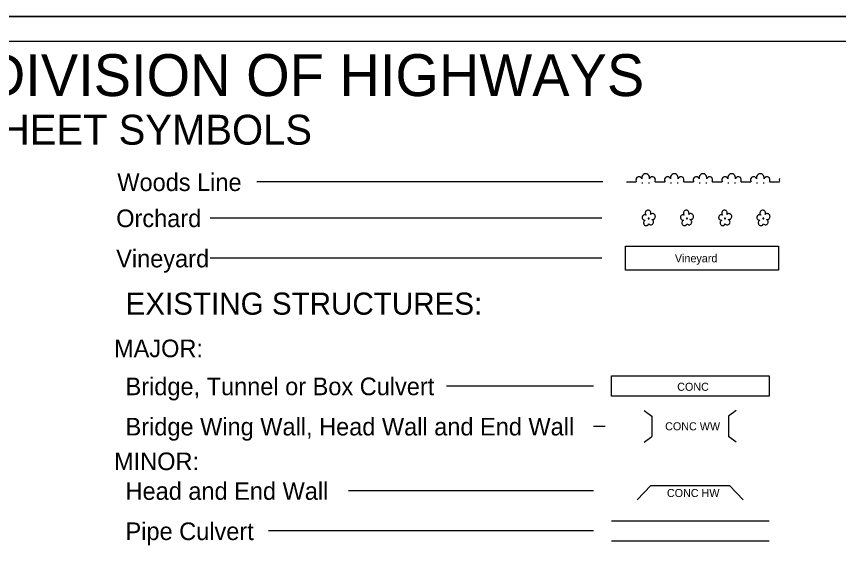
# Model space of a CAD drawing. Extents: x 2025847 to 2026166, y 840763 to 840870.
# Drawn here: x 2026094.71 to 2026130.13, y 840846.96 to 840870.09 of the extents above; entities that cross this region are included whole.
import ezdxf

# ---------------------------------------------------------------- set-up
doc = ezdxf.new("R2010")
doc.units = 0
for name, color, linetype in [('Sheet_Plan', 7, 'Continuous'), ('Sheet_Plot_Border_Outside_CELL', 7, 'Continuous'), ('Sheet_Symbology', 7, 'Continuous'), ('z - Construction', 7, 'Continuous')]:
    doc.layers.add(name, color=color, linetype=linetype)

msp = doc.modelspace()

# ---------------------------------------------------------------- linework, layer by layer
at = {"layer": 'Sheet_Plan'}
msp.add_line((2026164.548, 840869.009), (2026024.668, 840869.009), dxfattribs=at)
at = {"layer": 'Sheet_Plot_Border_Outside_CELL'}
msp.add_lwpolyline([(2026023.879, 840870.085), (2026165.546, 840870.085), (2026165.546, 840778.419), (2026023.879, 840778.419)], close=True, dxfattribs=at)
at = {"layer": 'Sheet_Symbology'}
for p, q in [((2026119.979, 840862.96), (2026105.07, 840862.96)), ((2026121, 840862.96), (2026121.411, 840862.96)), ((2026122.234, 840862.96), (2026122.646, 840862.96)), ((2026123.469, 840862.96), (2026123.881, 840862.96)), ((2026124.704, 840862.96), (2026125.115, 840862.96)), ((2026125.939, 840862.96), (2026126.35, 840862.96)), ((2026127.173, 840862.96), (2026127.585, 840862.96)), ((2026121.654, 840862.916), (2026121.695, 840862.916)), ((2026121.942, 840862.916), (2026121.983, 840862.916)), ((2026122.889, 840862.916), (2026122.93, 840862.916)), ((2026123.177, 840862.916), (2026123.218, 840862.916)), ((2026124.124, 840862.916), (2026124.165, 840862.916)), ((2026124.412, 840862.916), (2026124.453, 840862.916)), ((2026125.358, 840862.916), (2026125.399, 840862.916)), ((2026125.646, 840862.916), (2026125.688, 840862.916)), ((2026126.593, 840862.916), (2026126.634, 840862.916)), ((2026126.881, 840862.916), (2026126.922, 840862.916)), ((2026119.933, 840861.406), (2026103.063, 840861.406)), ((2026119.933, 840859.673), (2026103.063, 840859.673)), ((2026119.578, 840854.171), (2026113.242, 840854.171)), ((2026121.755, 840853.119), (2026122.092, 840852.871)), ((2026125.723, 840853.119), (2026125.385, 840852.871)), ((2026122.092, 840852.871), (2026122.092, 840852.004)), ((2026125.385, 840852.871), (2026125.385, 840852.004)), ((2026119.578, 840852.438), (2026120.071, 840852.438)), ((2026121.755, 840851.756), (2026122.092, 840852.004)), ((2026125.723, 840851.756), (2026125.385, 840852.004)), ((2026121.459, 840849.269), (2026122.041, 840849.882)), ((2026122.041, 840849.882), (2026125.437, 840849.882)), ((2026125.437, 840849.882), (2026126.019, 840849.269)), ((2026119.578, 840849.665), (2026109.016, 840849.665)), ((2026120.343, 840848.366), (2026127.134, 840848.366)), ((2026119.578, 840847.932), (2026105.568, 840847.932)), ((2026120.343, 840847.499), (2026127.134, 840847.499))]:
    msp.add_line(p, q, dxfattribs=at)
for points in [[(2026122.027, 840861.558), (2026122.04, 840861.584), (2026122.044, 840861.61), (2026122.04, 840861.636), (2026122.036, 840861.662), (2026122.023, 840861.684), (2026122.011, 840861.705), (2026121.99, 840861.723), (2026121.97, 840861.736), (2026121.941, 840861.744), (2026121.92, 840861.744), (2026121.896, 840861.74), (2026121.871, 840861.731), (2026121.85, 840861.718), (2026121.83, 840861.701), (2026121.817, 840861.675), (2026121.809, 840861.653), (2026121.805, 840861.627), (2026121.805, 840861.601), (2026121.809, 840861.575), (2026121.822, 840861.554), (2026121.838, 840861.528), (2026121.817, 840861.541), (2026121.793, 840861.545), (2026121.768, 840861.545), (2026121.747, 840861.536), (2026121.727, 840861.528), (2026121.706, 840861.51), (2026121.69, 840861.493), (2026121.677, 840861.471), (2026121.673, 840861.45), (2026121.669, 840861.419), (2026121.673, 840861.398), (2026121.682, 840861.376), (2026121.698, 840861.354), (2026121.71, 840861.337), (2026121.731, 840861.324), (2026121.756, 840861.311), (2026121.776, 840861.307), (2026121.801, 840861.307), (2026121.78, 840861.298), (2026121.76, 840861.281), (2026121.747, 840861.263), (2026121.739, 840861.237), (2026121.731, 840861.211), (2026121.731, 840861.19), (2026121.735, 840861.164), (2026121.747, 840861.142), (2026121.76, 840861.12), (2026121.776, 840861.103), (2026121.797, 840861.09), (2026121.817, 840861.081), (2026121.842, 840861.081), (2026121.867, 840861.081), (2026121.887, 840861.086), (2026121.908, 840861.103), (2026121.929, 840861.116), (2026121.949, 840861.155)], [(2026121.949, 840861.155), (2026121.998, 840861.125), (2026122.023, 840861.116), (2026122.048, 840861.112), (2026122.073, 840861.116), (2026122.093, 840861.125), (2026122.114, 840861.138), (2026122.134, 840861.155), (2026122.147, 840861.177), (2026122.155, 840861.198), (2026122.163, 840861.224), (2026122.159, 840861.25), (2026122.155, 840861.276), (2026122.138, 840861.302), (2026122.126, 840861.32), (2026122.105, 840861.333), (2026122.081, 840861.346), (2026122.105, 840861.341), (2026122.134, 840861.341), (2026122.155, 840861.35), (2026122.18, 840861.363), (2026122.2, 840861.376), (2026122.217, 840861.398), (2026122.229, 840861.424), (2026122.233, 840861.45), (2026122.237, 840861.476), (2026122.233, 840861.502), (2026122.225, 840861.528), (2026122.208, 840861.549), (2026122.188, 840861.571), (2026122.167, 840861.584), (2026122.143, 840861.593), (2026122.118, 840861.597), (2026122.093, 840861.597), (2026122.068, 840861.588), (2026122.048, 840861.575), (2026122.027, 840861.558)], [(2026123.674, 840861.558), (2026123.686, 840861.584), (2026123.69, 840861.61), (2026123.686, 840861.636), (2026123.682, 840861.662), (2026123.67, 840861.684), (2026123.657, 840861.705), (2026123.637, 840861.723), (2026123.616, 840861.736), (2026123.587, 840861.744), (2026123.567, 840861.744), (2026123.542, 840861.74), (2026123.517, 840861.731), (2026123.497, 840861.718), (2026123.476, 840861.701), (2026123.464, 840861.675), (2026123.455, 840861.653), (2026123.451, 840861.627), (2026123.451, 840861.601), (2026123.455, 840861.575), (2026123.468, 840861.554), (2026123.484, 840861.528), (2026123.464, 840861.541), (2026123.439, 840861.545), (2026123.414, 840861.545), (2026123.394, 840861.536), (2026123.373, 840861.528), (2026123.353, 840861.51), (2026123.336, 840861.493), (2026123.324, 840861.471), (2026123.32, 840861.45), (2026123.316, 840861.419), (2026123.32, 840861.398), (2026123.328, 840861.376), (2026123.344, 840861.354), (2026123.357, 840861.337), (2026123.377, 840861.324), (2026123.402, 840861.311), (2026123.423, 840861.307), (2026123.447, 840861.307), (2026123.427, 840861.298), (2026123.406, 840861.281), (2026123.394, 840861.263), (2026123.386, 840861.237), (2026123.377, 840861.211), (2026123.377, 840861.19), (2026123.381, 840861.164), (2026123.394, 840861.142), (2026123.406, 840861.12), (2026123.423, 840861.103), (2026123.443, 840861.09), (2026123.464, 840861.081), (2026123.488, 840861.081), (2026123.513, 840861.081), (2026123.534, 840861.086), (2026123.554, 840861.103), (2026123.575, 840861.116), (2026123.595, 840861.155)], [(2026123.595, 840861.155), (2026123.645, 840861.125), (2026123.67, 840861.116), (2026123.694, 840861.112), (2026123.719, 840861.116), (2026123.739, 840861.125), (2026123.76, 840861.138), (2026123.781, 840861.155), (2026123.793, 840861.177), (2026123.801, 840861.198), (2026123.809, 840861.224), (2026123.805, 840861.25), (2026123.801, 840861.276), (2026123.785, 840861.302), (2026123.772, 840861.32), (2026123.752, 840861.333), (2026123.727, 840861.346), (2026123.752, 840861.341), (2026123.781, 840861.341), (2026123.801, 840861.35), (2026123.826, 840861.363), (2026123.846, 840861.376), (2026123.863, 840861.398), (2026123.875, 840861.424), (2026123.879, 840861.45), (2026123.884, 840861.476), (2026123.879, 840861.502), (2026123.871, 840861.528), (2026123.855, 840861.549), (2026123.834, 840861.571), (2026123.814, 840861.584), (2026123.789, 840861.593), (2026123.764, 840861.597), (2026123.739, 840861.597), (2026123.715, 840861.588), (2026123.694, 840861.575), (2026123.674, 840861.558)], [(2026125.32, 840861.558), (2026125.332, 840861.584), (2026125.336, 840861.61), (2026125.332, 840861.636), (2026125.328, 840861.662), (2026125.316, 840861.684), (2026125.303, 840861.705), (2026125.283, 840861.723), (2026125.262, 840861.736), (2026125.234, 840861.744), (2026125.213, 840861.744), (2026125.188, 840861.74), (2026125.164, 840861.731), (2026125.143, 840861.718), (2026125.122, 840861.701), (2026125.11, 840861.675), (2026125.102, 840861.653), (2026125.098, 840861.627), (2026125.098, 840861.601), (2026125.102, 840861.575), (2026125.114, 840861.554), (2026125.131, 840861.528), (2026125.11, 840861.541), (2026125.085, 840861.545), (2026125.061, 840861.545), (2026125.04, 840861.536), (2026125.02, 840861.528), (2026124.999, 840861.51), (2026124.982, 840861.493), (2026124.97, 840861.471), (2026124.966, 840861.45), (2026124.962, 840861.419), (2026124.966, 840861.398), (2026124.974, 840861.376), (2026124.991, 840861.354), (2026125.003, 840861.337), (2026125.024, 840861.324), (2026125.048, 840861.311), (2026125.069, 840861.307), (2026125.094, 840861.307), (2026125.073, 840861.298), (2026125.052, 840861.281), (2026125.04, 840861.263), (2026125.032, 840861.237), (2026125.024, 840861.211), (2026125.024, 840861.19), (2026125.028, 840861.164), (2026125.04, 840861.142), (2026125.052, 840861.12), (2026125.069, 840861.103), (2026125.089, 840861.09), (2026125.11, 840861.081), (2026125.135, 840861.081), (2026125.159, 840861.081), (2026125.18, 840861.086), (2026125.201, 840861.103), (2026125.221, 840861.116), (2026125.242, 840861.155)], [(2026125.242, 840861.155), (2026125.291, 840861.125), (2026125.316, 840861.116), (2026125.341, 840861.112), (2026125.365, 840861.116), (2026125.386, 840861.125), (2026125.406, 840861.138), (2026125.427, 840861.155), (2026125.439, 840861.177), (2026125.448, 840861.198), (2026125.456, 840861.224), (2026125.452, 840861.25), (2026125.448, 840861.276), (2026125.431, 840861.302), (2026125.419, 840861.32), (2026125.398, 840861.333), (2026125.373, 840861.346), (2026125.398, 840861.341), (2026125.427, 840861.341), (2026125.448, 840861.35), (2026125.472, 840861.363), (2026125.493, 840861.376), (2026125.509, 840861.398), (2026125.522, 840861.424), (2026125.526, 840861.45), (2026125.53, 840861.476), (2026125.526, 840861.502), (2026125.518, 840861.528), (2026125.501, 840861.549), (2026125.48, 840861.571), (2026125.46, 840861.584), (2026125.435, 840861.593), (2026125.411, 840861.597), (2026125.386, 840861.597), (2026125.361, 840861.588), (2026125.341, 840861.575), (2026125.32, 840861.558)], [(2026126.966, 840861.558), (2026126.979, 840861.584), (2026126.983, 840861.61), (2026126.979, 840861.636), (2026126.975, 840861.662), (2026126.962, 840861.684), (2026126.95, 840861.705), (2026126.929, 840861.723), (2026126.909, 840861.736), (2026126.88, 840861.744), (2026126.859, 840861.744), (2026126.835, 840861.74), (2026126.81, 840861.731), (2026126.789, 840861.718), (2026126.769, 840861.701), (2026126.756, 840861.675), (2026126.748, 840861.653), (2026126.744, 840861.627), (2026126.744, 840861.601), (2026126.748, 840861.575), (2026126.761, 840861.554), (2026126.777, 840861.528), (2026126.756, 840861.541), (2026126.732, 840861.545), (2026126.707, 840861.545), (2026126.686, 840861.536), (2026126.666, 840861.528), (2026126.645, 840861.51), (2026126.629, 840861.493), (2026126.616, 840861.471), (2026126.612, 840861.45), (2026126.608, 840861.419), (2026126.612, 840861.398), (2026126.621, 840861.376), (2026126.637, 840861.354), (2026126.649, 840861.337), (2026126.67, 840861.324), (2026126.695, 840861.311), (2026126.715, 840861.307), (2026126.74, 840861.307), (2026126.719, 840861.298), (2026126.699, 840861.281), (2026126.686, 840861.263), (2026126.678, 840861.237), (2026126.67, 840861.211), (2026126.67, 840861.19), (2026126.674, 840861.164), (2026126.686, 840861.142), (2026126.699, 840861.12), (2026126.715, 840861.103), (2026126.736, 840861.09), (2026126.756, 840861.081), (2026126.781, 840861.081), (2026126.806, 840861.081), (2026126.826, 840861.086), (2026126.847, 840861.103), (2026126.868, 840861.116), (2026126.888, 840861.155)], [(2026126.888, 840861.155), (2026126.937, 840861.125), (2026126.962, 840861.116), (2026126.987, 840861.112), (2026127.012, 840861.116), (2026127.032, 840861.125), (2026127.053, 840861.138), (2026127.073, 840861.155), (2026127.086, 840861.177), (2026127.094, 840861.198), (2026127.102, 840861.224), (2026127.098, 840861.25), (2026127.094, 840861.276), (2026127.077, 840861.302), (2026127.065, 840861.32), (2026127.044, 840861.333), (2026127.02, 840861.346), (2026127.044, 840861.341), (2026127.073, 840861.341), (2026127.094, 840861.35), (2026127.119, 840861.363), (2026127.139, 840861.376), (2026127.156, 840861.398), (2026127.168, 840861.424), (2026127.172, 840861.45), (2026127.176, 840861.476), (2026127.172, 840861.502), (2026127.164, 840861.528), (2026127.147, 840861.549), (2026127.127, 840861.571), (2026127.106, 840861.584), (2026127.082, 840861.593), (2026127.057, 840861.597), (2026127.032, 840861.597), (2026127.007, 840861.588), (2026126.987, 840861.575), (2026126.966, 840861.558)], [(2026121.957, 840861.406), (2026121.945, 840861.406), (2026121.937, 840861.402), (2026121.929, 840861.398), (2026121.929, 840861.385), (2026121.929, 840861.376), (2026121.937, 840861.367), (2026121.949, 840861.367), (2026121.957, 840861.367), (2026121.966, 840861.376), (2026121.97, 840861.389), (2026121.966, 840861.398), (2026121.957, 840861.406)], [(2026123.604, 840861.406), (2026123.591, 840861.406), (2026123.583, 840861.402), (2026123.575, 840861.398), (2026123.575, 840861.385), (2026123.575, 840861.376), (2026123.583, 840861.367), (2026123.595, 840861.367), (2026123.604, 840861.367), (2026123.612, 840861.376), (2026123.616, 840861.389), (2026123.612, 840861.398), (2026123.604, 840861.406)], [(2026125.25, 840861.406), (2026125.238, 840861.406), (2026125.229, 840861.402), (2026125.221, 840861.398), (2026125.221, 840861.385), (2026125.221, 840861.376), (2026125.229, 840861.367), (2026125.242, 840861.367), (2026125.25, 840861.367), (2026125.258, 840861.376), (2026125.262, 840861.389), (2026125.258, 840861.398), (2026125.25, 840861.406)], [(2026126.896, 840861.406), (2026126.884, 840861.406), (2026126.876, 840861.402), (2026126.868, 840861.398), (2026126.868, 840861.385), (2026126.868, 840861.376), (2026126.876, 840861.367), (2026126.888, 840861.367), (2026126.896, 840861.367), (2026126.905, 840861.376), (2026126.909, 840861.389), (2026126.905, 840861.398), (2026126.896, 840861.406)], [(2026120.953, 840860.193), (2026127.538, 840860.193), (2026127.538, 840859.154), (2026120.953, 840859.154), (2026120.953, 840860.193)], [(2026120.343, 840854.604), (2026127.134, 840854.604), (2026127.134, 840853.737), (2026120.343, 840853.737), (2026120.343, 840854.604)]]:
    msp.add_lwpolyline(points, dxfattribs=at)
for centre, major_axis, start_param, end_param in [((2026121.819, 840863.134), (0, 0.179), 4.46741, 8.09896), ((2026123.053, 840863.134), (0, 0.179), 4.46741, 8.09896), ((2026124.288, 840863.134), (0, 0.179), 4.46741, 8.09896), ((2026125.523, 840863.134), (0, 0.179), 4.46741, 8.09896), ((2026126.757, 840863.134), (0, 0.179), 4.46741, 8.09896), ((2026121.531, 840863.048), (0, 0.137), 5.03414, 8.538701), ((2026122.107, 840863.048), (0, 0.137), 4.02767, 7.532231), ((2026122.765, 840863.048), (0, 0.137), 5.03414, 8.538701), ((2026123.341, 840863.048), (0, 0.137), 4.02767, 7.532231), ((2026124, 840863.048), (0, 0.137), 5.03414, 8.538701), ((2026124.576, 840863.048), (0, 0.137), 4.02767, 7.532231), ((2026125.235, 840863.048), (0, 0.137), 5.03414, 8.538701), ((2026125.811, 840863.048), (0, 0.137), 4.02767, 7.532231), ((2026126.469, 840863.048), (0, 0.137), 5.03414, 8.538701), ((2026127.046, 840863.048), (0, 0.137), 4.02767, 7.532231), ((2026127.704, 840863.048), (0, 0.137), 1.156298, 1.985294)]:
    msp.add_ellipse(centre, major_axis=major_axis, ratio=0.95, start_param=start_param, end_param=end_param, dxfattribs=at)
at = {"layer": 'z - Construction'}
msp.add_line((2026165.546, 840870.085), (2026023.879, 840870.085), dxfattribs=at)

# ---------------------------------------------------------------- texts
at = {"layer": 'Sheet_Symbology'}
for s, height, p in [('STATE OF NORTH CAROLINA, DIVISION OF HIGHWAYS', 1.80351, (2026057.976, 840866.657)), ('CONVENTIONAL  PLAN SHEET SYMBOLS', 1.28822, (2026073.367, 840864.564)), ('Woods Line', 0.7582, (2026099.058, 840862.568)), ('Orchard', 0.7582, (2026099.011, 840861.014)), ('Vineyard', 0.7582, (2026099.011, 840859.281)), ('EXISTING STRUCTURES:', 0.95314, (2026099.413, 840857.242)), ('MAJOR:', 0.7582, (2026098.917, 840855.413)), ('Bridge, Tunnel or Box Culvert', 0.75818, (2026099.413, 840853.776)), ('CONC', 0.3466, (2026123.178, 840853.966)), ('Bridge Wing Wall, Head Wall and End Wall', 0.75818, (2026099.413, 840852.043)), ('MINOR:', 0.7582, (2026098.917, 840850.55)), ('Head and End Wall', 0.75818, (2026099.413, 840849.271)), ('CONC HW', 0.3466, (2026122.735, 840849.391)), ('Pipe Culvert', 0.75818, (2026099.413, 840847.539))]:
    msp.add_text(s, height=height, dxfattribs=at).set_placement(p)
for s, p in [('Vineyard', (2026123.079, 840859.5)), ('CONC WW', (2026122.658, 840852.264))]:
    msp.add_text(s, height=0.3466, rotation=0, dxfattribs=at).set_placement(p)

doc.saveas('drawing.dxf')
